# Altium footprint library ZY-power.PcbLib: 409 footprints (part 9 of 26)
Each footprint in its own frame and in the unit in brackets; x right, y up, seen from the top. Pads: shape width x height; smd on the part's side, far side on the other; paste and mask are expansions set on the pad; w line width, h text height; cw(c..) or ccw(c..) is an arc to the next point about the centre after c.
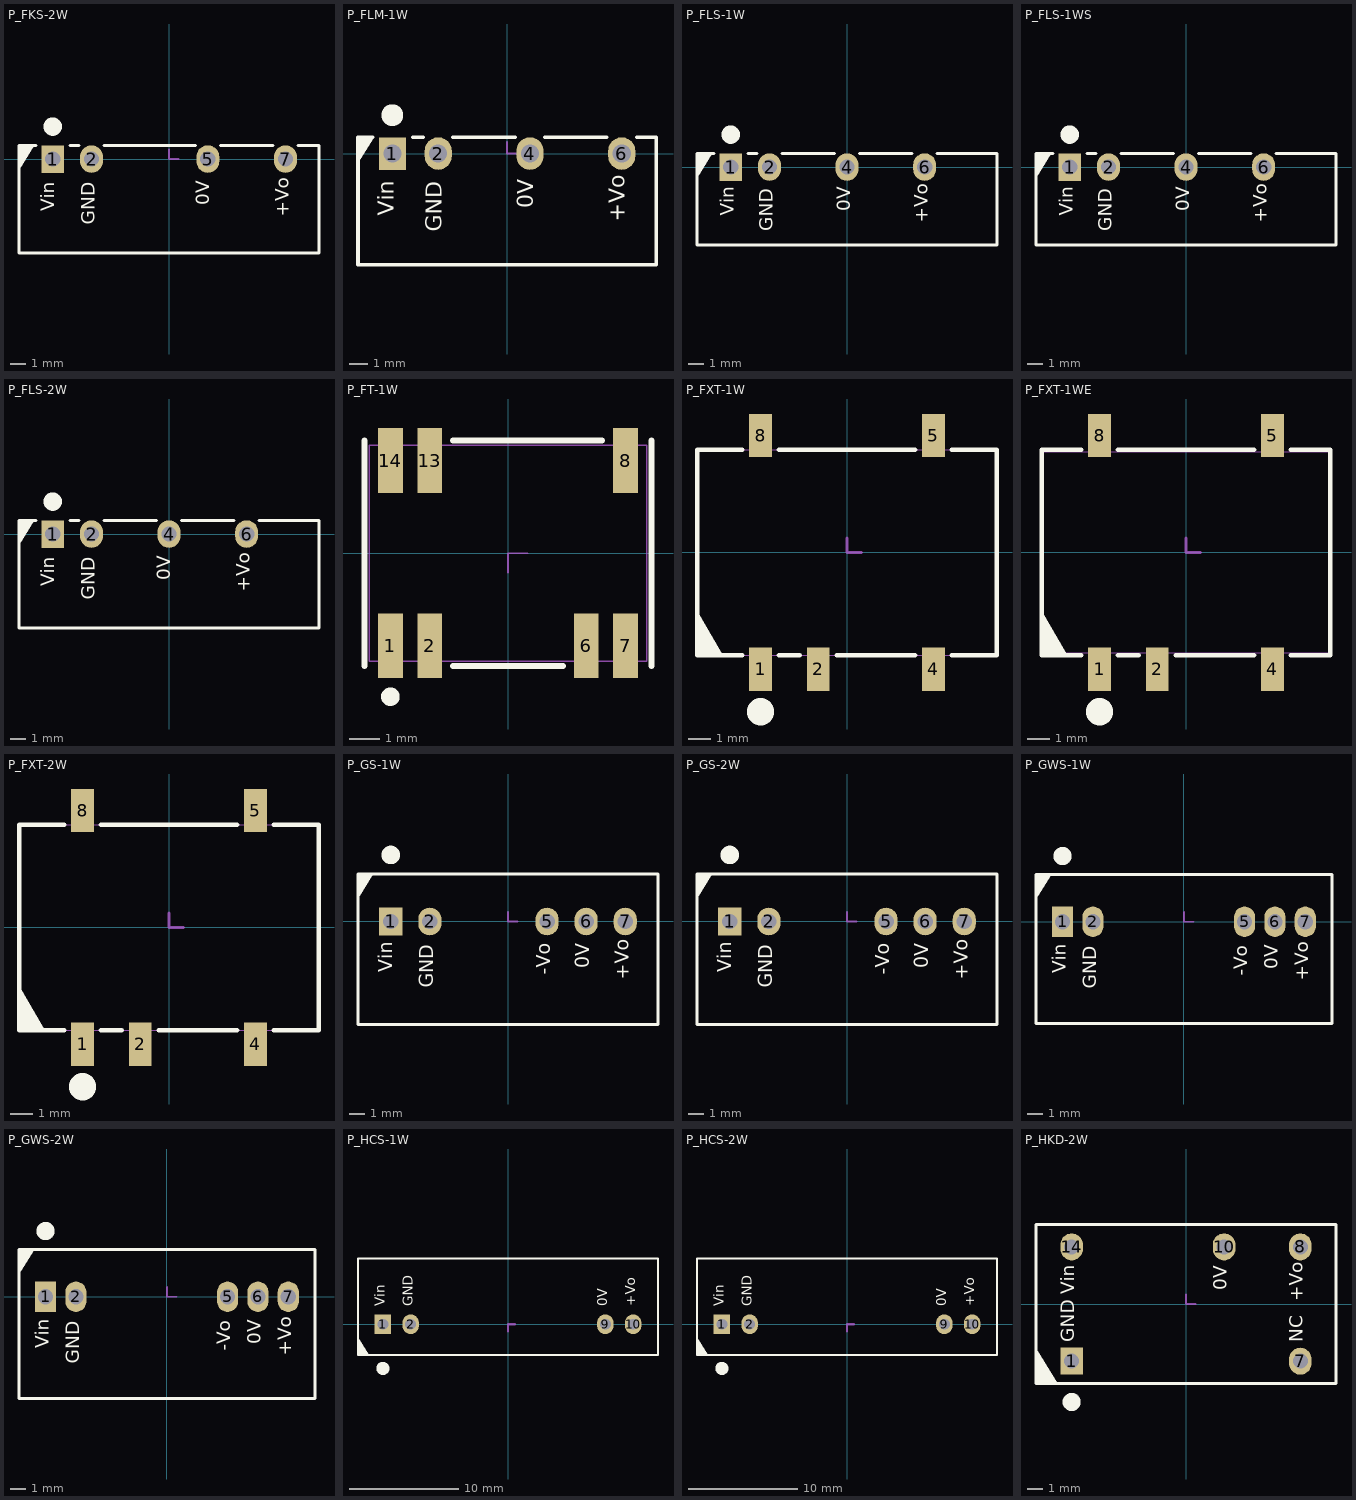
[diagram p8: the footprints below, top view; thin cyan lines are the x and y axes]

## P_FKS-2W [mm]
height 10.1
pads (4):
  rect 1.5x1.8 hole 1: 1(-7.62,0)
  oval 1.5x1.8 hole 1: 2(-5.08,0) 5(2.54,0) 7(7.62,0)
Top Overlay:
  circle w1: c-7.62,2.125 r0.1
  region: -9.83,-0.686 -9.83,0.9 -8.836,0.9
  lines w0.2: -8.72,0.9 -9.83,0.9 -9.83,-6.15 9.82,-6.15 9.82,0.9 8.44,0.9 ; -6.5,0.9 -5.9,0.9 ; -4.26,0.9 1.72,0.9 ; 3.36,0.9 6.8,0.9
  text "Vin" at -7.239,-3.435 h1.52
  text "GND" at -4.572,-4.318 h1.52
  text "0V" at 2.921,-3.036 h1.52
  text "+Vo" at 8.128,-3.776 h1.52
Mechanical 15:
  lines w0.127: 0,0.635 0,0 0.635,0
3D body "zhenjao01.stp": height 8.36, standoff -4.08, extent -8.32,-1.48 -6.92,0.12
3D body "zhenjao01.stp": height 8.36, standoff -4.08, extent -5.78,-1.48 -4.38,0.12
3D body "zhenjao01.stp": height 8.36, standoff -4.08, extent 1.84,-1.48 3.24,0.12
3D body "zhenjao01.stp": height 8.36, standoff -4.08, extent 6.92,-1.48 8.32,0.12
3D body: height 10.1, standoff 0, extent -9.83,-6.15 9.82,0.9

## P_FLM-1W [mm]
height 7.5
pads (4):
  rect 1.5x1.8 hole 1: 1(-6.35,0)
  oval 1.5x1.8 hole 1: 2(-3.81,0) 4(1.27,0) 6(6.35,0)
Top Overlay:
  circle w1: c-6.35,2.125 r0.1
  region: -8.25,-0.544 -8.25,0.864 -7.368,0.864
  lines w0.2: -7.45,0.9 -8.25,0.9 -8.25,-6.15 8.25,-6.15 8.25,0.9 7.17,0.9 ; -5.23,0.9 -4.63,0.9 ; -2.99,0.9 0.45,0.9 ; 2.09,0.9 5.53,0.9
  text "+Vo" at 6.833,-3.776 h1.52
  text "0V" at 1.753,-3.036 h1.52
  text "GND" at -3.302,-4.318 h1.52
  text "Vin" at -5.969,-3.435 h1.52
Mechanical 15:
  lines w0.127: 0,0.635 0,0 0.635,0

## P_FLS-1W [mm]
height 10.16
pads (4):
  rect 1.5x1.8 hole 1: 1(-7.62,0)
  oval 1.5x1.8 hole 1: 2(-5.08,0) 4(0,0) 6(5.08,0)
Top Overlay:
  circle w1: c-7.62,2.125 r0.1
  region: -9.83,-0.686 -9.83,0.9 -8.836,0.9
  lines w0.2: -8.72,0.9 -9.83,0.9 -9.83,-5.1 9.82,-5.1 9.82,0.9 5.9,0.9 ; -6.5,0.9 -5.9,0.9 ; -4.26,0.9 -0.82,0.9 ; 0.82,0.9 4.26,0.9
  text "Vin" at -7.112,-3.181 h1.52
  text "GND" at -4.572,-4.191 h1.52
  text "0V" at 0.508,-2.909 h1.52
  text "+Vo" at 5.588,-3.649 h1.52
Mechanical 15:
  lines w0.127: 0,0.635 0,0 0.635,0
3D body "zhenjao01.stp": height 8.36, standoff -4.08, extent -8.32,-1.48 -6.92,0.12
3D body "zhenjao01.stp": height 8.36, standoff -4.08, extent -5.78,-1.48 -4.38,0.12
3D body "zhenjao01.stp": height 8.36, standoff -4.08, extent -0.7,-1.48 0.7,0.12
3D body "zhenjao01.stp": height 8.36, standoff -4.08, extent 4.38,-1.48 5.78,0.12
3D body: height 10.16, standoff 0, extent -9.83,-5.1 9.82,0.9

## P_FLS-1WS [mm]
height 10.16
pads (4):
  rect 1.5x1.8 hole 1: 1(-7.62,0)
  oval 1.5x1.8 hole 1: 2(-5.08,0) 4(0,0) 6(5.08,0)
Top Overlay:
  circle w1: c-7.62,2.125 r0.1
  region: -9.83,-0.686 -9.83,0.9 -8.836,0.9
  lines w0.2: -8.72,0.9 -9.83,0.9 -9.83,-5.1 9.82,-5.1 9.82,0.9 5.9,0.9 ; -6.5,0.9 -5.9,0.9 ; -4.26,0.9 -0.82,0.9 ; 0.82,0.9 4.26,0.9
  text "+Vo" at 5.588,-3.649 h1.52
  text "0V" at 0.508,-2.909 h1.52
  text "GND" at -4.572,-4.191 h1.52
  text "Vin" at -7.112,-3.181 h1.52
Mechanical 15:
  lines w0.127: 0,0.635 0,0 0.635,0
3D body: height 10.16, standoff 0, extent -9.83,-5.1 9.82,0.9
3D body "zhenjao01.stp": height 8.36, standoff -4.08, extent 4.38,-1.48 5.78,0.12
3D body "zhenjao01.stp": height 8.36, standoff -4.08, extent -0.7,-1.48 0.7,0.12
3D body "zhenjao01.stp": height 8.36, standoff -4.08, extent -5.78,-1.48 -4.38,0.12
3D body "zhenjao01.stp": height 8.36, standoff -4.08, extent -8.32,-1.48 -6.92,0.12

## P_FLS-2W [mm]
height 10.16
pads (4):
  rect 1.5x1.8 hole 1: 1(-7.62,0)
  oval 1.5x1.8 hole 1: 2(-5.08,0) 4(0,0) 6(5.08,0)
Top Overlay:
  circle w1: c-7.62,2.125 r0.1
  region: -9.83,-0.686 -9.83,0.9 -8.836,0.9
  lines w0.2: -8.72,0.9 -9.83,0.9 -9.83,-6.15 9.82,-6.15 9.82,0.9 5.9,0.9 ; -6.5,0.9 -5.9,0.9 ; -4.26,0.9 -0.82,0.9 ; 0.82,0.9 4.26,0.9
  text "Vin" at -7.239,-3.435 h1.52
  text "GND" at -4.572,-4.318 h1.52
  text "0V" at 0.381,-3.036 h1.52
  text "+Vo" at 5.588,-3.776 h1.52
Mechanical 15:
  lines w0.127: 0,0.635 0,0 0.635,0
3D body "zhenjao01.stp": height 8.36, standoff -4.08, extent -8.32,-1.48 -6.92,0.12
3D body "zhenjao01.stp": height 8.36, standoff -4.08, extent -5.78,-1.48 -4.38,0.12
3D body "zhenjao01.stp": height 8.36, standoff -4.08, extent -0.7,-1.48 0.7,0.12
3D body "zhenjao01.stp": height 8.36, standoff -4.08, extent 4.38,-1.48 5.78,0.12
3D body: height 10.16, standoff 0, extent -9.83,-6.15 9.82,0.9

## P_FT-1W [mm] "20230306新修订"
height 3
pads (7):
  rect 0.8x2.1 smd: 1(-3.81,-3) 2(-2.54,-3) 6(2.54,-3) 7(3.81,-3) 8(3.81,3) 13(-2.54,3) 14(-3.81,3)
Top Overlay:
  circle w0.4: c-3.81,-4.649 r0.1
  lines w0.2: -4.65,-3.65 -4.65,3.65 ; -1.778,-3.65 1.778,-3.65 ; -1.778,3.65 3.048,3.65 ; 4.65,-3.65 4.65,3.65
Mechanical 13:
  lines w0.05: -4.5,-3.5 -4.5,3.5 4.5,3.5 4.5,-3.5 -4.5,-3.5
Mechanical 15:
  lines w0.05: 0,-0.635 0,0 0.635,0
3D body "P0505FT-1W.stp": height 3.01, standoff -0.01, extent -4.5,-3.5 4.5,3.5

## P_FXT-1W [mm]
height 7.25
pads (5):
  rect 1x1.9 smd: 1(-3.81,-5.15) 2(-1.27,-5.15) 4(3.81,-5.15) 5(3.81,5.15) 8(-3.81,5.15)
Top Overlay:
  circle w1: c-3.812,-7.023 r0.1
  region: -5.484,-4.53 -6.6,-2.591 -6.6,-4.53
  lines w0.2: -4.623,-4.53 -6.6,-4.53 -6.6,4.53 -4.623,4.53 ; -2.997,-4.53 -2.084,-4.53 ; -2.997,4.53 2.997,4.53 ; -0.456,-4.53 2.997,-4.53 ; 4.623,-4.53 6.6,-4.53 6.6,4.53 4.623,4.53
Mechanical 15:
  lines w0.051: -6.6,-4.53 6.6,-4.53 6.6,4.53 -6.6,4.53 -6.6,-4.53
  lines w0.127: 0,0.635 0,0 0.635,0

## P_FXT-1WE [mm]
height 7
pads (5):
  rect 1x1.9 smd: 1(-3.81,-5.15) 2(-1.27,-5.15) 4(3.81,-5.15) 5(3.81,5.15) 8(-3.81,5.15)
Top Overlay:
  circle w1: c-3.812,-7.023 r0.1
  region: -5.234,-4.53 -6.35,-2.591 -6.35,-4.53
  lines w0.2: -4.623,-4.53 -6.35,-4.53 -6.35,4.53 -4.623,4.53 ; -2.997,-4.53 -2.084,-4.53 ; -2.997,4.53 2.997,4.53 ; -0.456,-4.53 2.997,-4.53 ; 4.623,-4.53 6.35,-4.53 6.35,4.53 4.623,4.53
Mechanical 15:
  lines w0.051: -6.35,-4.43 6.35,-4.43 6.35,4.43 -6.35,4.43 -6.35,-4.43
  lines w0.127: 0,0.635 0,0 0.635,0

## P_FXT-2W [mm]
height 7.25
pads (5):
  rect 1x1.9 smd: 1(-3.81,-5.15) 2(-1.27,-5.15) 4(3.81,-5.15) 5(3.81,5.15) 8(-3.81,5.15)
Top Overlay:
  circle w1: c-3.812,-7.023 r0.1
  region: -5.484,-4.53 -6.6,-2.591 -6.6,-4.53
  lines w0.2: -4.623,-4.53 -6.6,-4.53 -6.6,4.53 -4.623,4.53 ; -2.997,-4.53 -2.084,-4.53 ; -2.997,4.53 2.997,4.53 ; -0.456,-4.53 2.997,-4.53 ; 4.623,-4.53 6.6,-4.53 6.6,4.53 4.623,4.53
Mechanical 15:
  lines w0.051: -6.6,-4.53 -6.6,4.53 6.6,4.53 6.6,-4.53 -6.6,-4.53
  lines w0.127: 0,0.635 0,0 0.635,0

## P_GS-1W [mm]
height 12.5
pads (5):
  rect 1.5x1.8 hole 1: 1(-7.62,0)
  oval 1.5x1.8 hole 1: 2(-5.08,0) 5(2.54,0) 6(5.08,0) 7(7.62,0)
Top Overlay:
  circle w1: c-7.62,4.325 r0.1
  region: -9.75,1.514 -9.75,3.1 -8.756,3.1
  lines w0.2: -9.75,-6.7 -9.75,3.1 9.75,3.1 9.75,-6.7 -9.75,-6.7
  text "+Vo" at 8.128,-3.775 h1.52
  text "0V" at 5.568,-3.037 h1.52
  text "-Vo" at 3.048,-3.465 h1.52
  text "GND" at -4.572,-4.321 h1.52
  text "Vin" at -7.239,-3.307 h1.52
Mechanical 15:
  lines w0.127: 0,0.635 0,0 0.635,0
3D body: height 12.5, standoff 0, extent -9.75,-6.7 9.75,3.1
3D body "zhenjao01.stp": height 8.36, standoff -4.08, extent -8.32,-1.48 -6.92,0.12
3D body "zhenjao01.stp": height 8.36, standoff -4.08, extent -5.78,-1.48 -4.38,0.12
3D body "zhenjao01.stp": height 8.36, standoff -4.08, extent 1.84,-1.48 3.24,0.12
3D body "zhenjao01.stp": height 8.36, standoff -4.08, extent 4.38,-1.48 5.78,0.12
3D body "zhenjao01.stp": height 8.36, standoff -4.08, extent 6.92,-1.48 8.32,0.12

## P_GS-2W [mm]
height 12.5
pads (5):
  rect 1.5x1.8 hole 1: 1(-7.62,0)
  oval 1.5x1.8 hole 1: 2(-5.08,0) 5(2.54,0) 6(5.08,0) 7(7.62,0)
Top Overlay:
  circle w1: c-7.62,4.325 r0.1
  region: -9.75,1.514 -9.75,3.1 -8.756,3.1
  lines w0.2: -9.75,-6.7 9.75,-6.7 9.75,3.1 -9.75,3.1 -9.75,-6.7
  text "Vin" at -7.239,-3.307 h1.52
  text "GND" at -4.572,-4.321 h1.52
  text "-Vo" at 3.048,-3.465 h1.52
  text "0V" at 5.568,-3.037 h1.52
  text "+Vo" at 8.128,-3.775 h1.52
Mechanical 15:
  lines w0.127: 0,0.635 0,0 0.635,0
3D body: height 12.5, standoff 0, extent -9.75,-6.7 9.75,3.1
3D body "zhenjao01.stp": height 8.36, standoff -4.08, extent -8.32,-1.48 -6.92,0.12
3D body "zhenjao01.stp": height 8.36, standoff -4.08, extent -5.78,-1.48 -4.38,0.12
3D body "zhenjao01.stp": height 8.36, standoff -4.08, extent 1.84,-1.48 3.24,0.12
3D body "zhenjao01.stp": height 8.36, standoff -4.08, extent 4.38,-1.48 5.78,0.12
3D body "zhenjao01.stp": height 8.36, standoff -4.08, extent 6.92,-1.48 8.32,0.12

## P_GWS-1W [mm]
height 12.5
pads (5):
  rect 1.4x2 hole 1: 1(-8,0)
  oval 1.4x2 hole 1: 2(-6,0) 5(4,0) 6(6,0) 7(8,0)
Top Overlay:
  circle w1: c-8,4.325 r0.1
  region: -9.75,1.514 -9.75,3.1 -8.756,3.1
  lines w0.2: -9.75,-6.7 -9.75,3.1 9.75,3.1 9.75,-6.7 -9.75,-6.7
  text "+Vo" at 8.5,-3.875 h1.52
  text "0V" at 6.48,-3.137 h1.52
  text "-Vo" at 4.46,-3.565 h1.52
  text "GND" at -5.475,-4.421 h1.52
  text "Vin" at -7.492,-3.407 h1.52
Mechanical 15:
  lines w0.127: 0,0.635 0,0 0.635,0
3D body "zhenjao01.stp": height 8.36, standoff -4.08, extent 7.3,-1.48 8.7,0.12
3D body "zhenjao01.stp": height 8.36, standoff -4.08, extent 5.3,-1.48 6.7,0.12
3D body "zhenjao01.stp": height 8.36, standoff -4.08, extent 3.3,-1.48 4.7,0.12
3D body "zhenjao01.stp": height 8.36, standoff -4.08, extent -6.7,-1.48 -5.3,0.12
3D body "zhenjao01.stp": height 8.36, standoff -4.08, extent -8.7,-1.48 -7.3,0.12
3D body: height 12.5, standoff 0, extent -9.75,-6.7 9.75,3.1

## P_GWS-2W [mm]
height 12.5
pads (5):
  rect 1.4x2 hole 1: 1(-8,0)
  oval 1.4x2 hole 1: 2(-6,0) 5(4,0) 6(6,0) 7(8,0)
Top Overlay:
  circle w1: c-8,4.325 r0.1
  region: -9.75,1.514 -9.75,3.1 -8.756,3.1
  lines w0.2: -9.75,-6.7 9.75,-6.7 9.75,3.1 -9.75,3.1 -9.75,-6.7
  text "Vin" at -7.492,-3.407 h1.52
  text "GND" at -5.475,-4.421 h1.52
  text "-Vo" at 4.46,-3.565 h1.52
  text "0V" at 6.48,-3.137 h1.52
  text "+Vo" at 8.5,-3.875 h1.52
Mechanical 15:
  lines w0.127: 0,0.635 0,0 0.635,0
3D body: height 12.5, standoff 0, extent -9.75,-6.7 9.75,3.1
3D body "zhenjao01.stp": height 8.36, standoff -4.08, extent -8.7,-1.48 -7.3,0.12
3D body "zhenjao01.stp": height 8.36, standoff -4.08, extent -6.7,-1.48 -5.3,0.12
3D body "zhenjao01.stp": height 8.36, standoff -4.08, extent 3.3,-1.48 4.7,0.12
3D body "zhenjao01.stp": height 8.36, standoff -4.08, extent 5.3,-1.48 6.7,0.12
3D body "zhenjao01.stp": height 8.36, standoff -4.08, extent 7.3,-1.48 8.7,0.12

## P_HCS-1W [mm]
height 11.4
pads (4):
  rect 1.5x1.8 hole 1: 1(-11.43,0)
  oval 1.5x1.8 hole 1: 2(-8.89,0) 9(8.89,0) 10(11.43,0)
Top Overlay:
  circle w1: c-11.43,-4.025 r0.1
  region: -13.7,-1.214 -13.7,-2.8 -12.706,-2.8
  lines w0.2: -13.7,-2.8 -13.7,6 13.7,6 13.7,-2.8 -13.7,-2.8
  text "+Vo" at 11.925,1.625 h1.52
  text "0V" at 9.385,1.625 h1.52
  text "GND" at -8.395,1.625 h1.52
  text "Vin" at -10.935,1.626 h1.52
Mechanical 15:
  lines w0.203: 0,-0.635 0,0 0.635,0
3D body "zhenjao01.stp": height 8.36, standoff -4.08, extent -9.59,-0.12 -8.19,1.48
3D body "zhenjao01.stp": height 8.36, standoff -4.08, extent -12.13,-0.12 -10.73,1.48
3D body "zhenjao01.stp": height 8.36, standoff -4.08, extent 8.19,-0.12 9.59,1.48
3D body "zhenjao01.stp": height 8.36, standoff -4.08, extent 10.73,-0.12 12.13,1.48
3D body: height 10.1, standoff 0, extent -13.7,-2.8 13.7,6

## P_HCS-2W [mm]
height 11.4
pads (4):
  rect 1.5x1.8 hole 1: 1(-11.43,0)
  oval 1.5x1.8 hole 1: 2(-8.89,0) 9(8.89,0) 10(11.43,0)
Top Overlay:
  circle w1: c-11.43,-4.025 r0.1
  region: -13.7,-1.214 -13.7,-2.8 -12.706,-2.8
  lines w0.2: -13.7,-2.8 13.7,-2.8 13.7,6 -13.7,6 -13.7,-2.8
  text "Vin" at -10.935,1.626 h1.52
  text "GND" at -8.395,1.625 h1.52
  text "0V" at 9.385,1.625 h1.52
  text "+Vo" at 11.925,1.625 h1.52
Mechanical 15:
  lines w0.203: 0,-0.635 0,0 0.635,0
3D body: height 10.1, standoff 0, extent -13.7,-2.8 13.7,6
3D body "zhenjao01.stp": height 8.36, standoff -4.08, extent 10.73,-0.12 12.13,1.48
3D body "zhenjao01.stp": height 8.36, standoff -4.08, extent 8.19,-0.12 9.59,1.48
3D body "zhenjao01.stp": height 8.36, standoff -4.08, extent -12.13,-0.12 -10.73,1.48
3D body "zhenjao01.stp": height 8.36, standoff -4.08, extent -9.59,-0.12 -8.19,1.48

## P_HKD-2W [mm]
height 8.5
pads (5):
  rect 1.5x1.8 hole 1: 1(-7.62,-3.81)
  oval 1.5x1.8 hole 1: 7(7.62,-3.81) 8(7.62,3.81) 10(2.54,3.81) 14(-7.62,3.81)
Top Overlay:
  circle w1: c-7.62,-6.525 r0.1
  region: -10,-2.97 -10,-5.3 -8.54,-5.3
  lines w0.2: -10,-5.3 10,-5.3 10,5.3 -10,5.3 -10,-5.3
  text "GND" at -7.138,-2.557 h1.52
  text "NC" at 8.082,-2.557 h1.52
  text "Vin" at -7.138,0.645 h1.52
  text "+Vo" at 8.082,0.177 h1.52
  text "0V" at 3.002,0.916 h1.52
Mechanical 15:
  lines w0.127: 0,0.635 0,0 0.635,0
3D body: height 0, standoff -4.91, extent 2.317,3.586 2.765,4.035
3D body: height 0, standoff -4.91, extent 7.397,3.586 7.845,4.035
3D body: height 0, standoff -4.91, extent 7.397,-4.034 7.845,-3.585
3D body: height 0, standoff -4.91, extent -7.843,3.586 -7.395,4.035
3D body: height 0, standoff -4.91, extent -7.843,-4.034 -7.395,-3.585
3D body: height 8.5, standoff 0, extent -10,-5.3 10,5.3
